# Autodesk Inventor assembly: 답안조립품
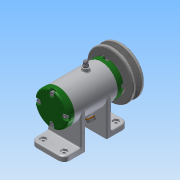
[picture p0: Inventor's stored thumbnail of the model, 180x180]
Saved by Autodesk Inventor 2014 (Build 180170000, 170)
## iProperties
Created: 2017-02
Part Number: 답안조립품
Document SubType Name: Assembly
Designer: 601-
Author: 601-
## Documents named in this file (16)
- C:\Users\601-\Desktop\470208V1020\답안조립품.iam
- C:\Users\601-\Desktop\470208V1020\1 본체.ipt
- C:\Users\601-\Desktop\470208V1020\V벨트풀리.ipt
- C:\Users\601-\Desktop\470208V1020\너트 M 8.ipt
- C:\Users\601-\Desktop\470208V1020\니플 M 6 x 0.75.ipt
- C:\Users\601-\Desktop\470208V1020\뒤커버.ipt
- C:\Users\601-\Desktop\470208V1020\베어링 15 x 32 x 9.ipt
- C:\Users\601-\Desktop\470208V1020\볼트 M 6 x 8.ipt
- C:\Users\601-\Desktop\470208V1020\볼트 M4 x 12.ipt
- C:\Users\601-\Desktop\470208V1020\스프링와셔 8.ipt
- C:\Users\601-\Desktop\470208V1020\앞커버.ipt
- C:\Users\601-\Desktop\470208V1020\오일 실 15 25 7.ipt
- C:\Users\601-\Desktop\470208V1020\와셔 6x11.5.ipt
- C:\Users\601-\Desktop\470208V1020\와셔 8x17.ipt
- C:\Users\601-\Desktop\470208V1020\축.ipt
- C:\Users\601-\Desktop\470208V1020\키 3 x 3 x 12.ipt
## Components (12 placed, 4 different names)
1. 1 본체:1
2. V벨트풀리:1
3. KS B 2023 6002 - 15 x 32 x 9:1
4. KS B 2023 6002 - 15 x 32 x 9:2
5. ISO 4762 M4 x 12:1
6. ISO 4762 M4 x 12:2
7. ISO 4762 M4 x 12:3
8. ISO 4762 M4 x 12:4
9. ISO 4762 M4 x 12:5
10. ISO 4762 M4 x 12:6
11. ISO 4762 M4 x 12:7
12. ISO 4762 M4 x 12:8
